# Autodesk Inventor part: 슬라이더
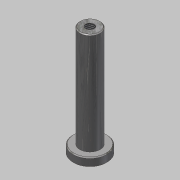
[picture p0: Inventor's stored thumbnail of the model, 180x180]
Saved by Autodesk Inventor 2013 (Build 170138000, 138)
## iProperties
Created: 2016-02
Part Number: 슬라이더
Material: 스테인리스강
Document SubType Name: Modeling
Designer: mduedu
Density: 8.08 g/cm^3
Mass: 65.4431 g
Surface Area: 33.4413 cm^2
Volume: 8.0994 cm^3
Author: mduedu
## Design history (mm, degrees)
sketch "스케치1"
  geometry: C1 r 10 at (0, 0); 1 further point
  constraints: 1 centre point, 1 coincident
  dimensions: "d0" = 20 diameter of C1
extrude "돌출1" new body sketch "스케치1" distance "d1" = 5; taper "d2" = 0 deg
sketch "스케치2"
  geometry: C1 r 6 at (0, 0); 1 further point
  constraints: 1 centre point, 1 coincident
  dimensions: "d3" = 12 diameter of C1
extrude "돌출2" join sketch "스케치2" distance "d4" = 60; taper "d5" = 0 deg
chamfer "모따기1" distance "d6" = 0.5; stored, may be unused: second distance "d7" = 2, angle "d8" = 45 deg
hole "구멍1" diameter "d11" = 4.917; stored, may be unused: countersink angle "d15" = 90 deg, drill point angle "d17" = 118 deg; dims "d9" = 10, "d10" = 10, "d12" = 10, "d13" = 4, "d14" = 2, "d16" = 12
chamfer "모따기2" distance "d18" = 0.5; stored, may be unused: second distance "d19" = 2, angle "d20" = 45 deg
node "솔리드1"
